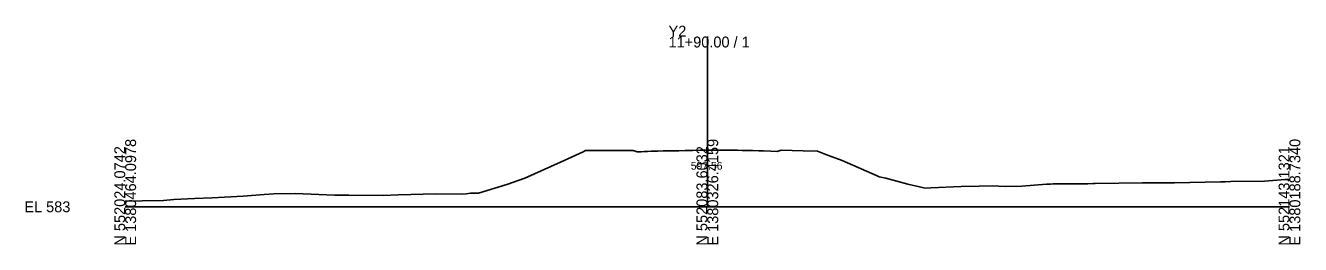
# Model space of a CAD drawing. Extents: x -26 to 303, y -10 to 2047.
# Drawn here: x -25.7 to 302.8, y 1990.3 to 2046.6 of the extents above; entities that cross this region are included whole.
import ezdxf

# ---------------------------------------------------------------- set-up
doc = ezdxf.new("R2010")
doc.units = 0
for name, color, linetype in [('Exist Cross Section Cell', 7, 'Continuous'), ('Exist XS Center Line Elevation Label', 7, 'Continuous'), ('Exist XS Ground Line', 7, 'Continuous')]:
    doc.layers.add(name, color=color, linetype=linetype)

msp = doc.modelspace()

# ---------------------------------------------------------------- linework, layer by layer
at = {"layer": 'Exist Cross Section Cell'}
for p, q in [((150, 2000), (150, 2043.8)), ((0, 2000), (150, 2000)), ((150, 2000), (300, 2000))]:
    msp.add_line(p, q, dxfattribs=at)
at = {"layer": 'Exist XS Ground Line'}
for p, q in [((112.15, 2011.49), (118.01, 2014.14)), ((118.01, 2014.14), (118.57, 2014.45)), ((118.57, 2014.45), (122.81, 2014.46)), ((122.81, 2014.46), (130.89, 2014.49)), ((130.89, 2014.49), (131.93, 2014.11)), ((131.93, 2014.11), (132.98, 2014.17)), ((132.98, 2014.17), (133.71, 2014.22)), ((133.71, 2014.22), (134.57, 2014.27)), ((134.57, 2014.27), (135.51, 2014.3)), ((135.51, 2014.3), (137.21, 2014.35)), ((137.21, 2014.35), (138.59, 2014.37)), ((138.59, 2014.37), (139.93, 2014.39)), ((139.93, 2014.39), (141.76, 2014.42)), ((141.76, 2014.42), (142.67, 2014.43)), ((142.67, 2014.43), (144.3, 2014.45)), ((144.3, 2014.45), (145.39, 2014.47)), ((145.39, 2014.47), (146.19, 2014.5)), ((146.19, 2014.5), (148.17, 2014.54)), ((148.17, 2014.54), (150, 2014.56)), ((150, 2014.56), (150.82, 2014.57)), ((150.82, 2014.57), (152.92, 2014.56)), ((152.92, 2014.56), (153.53, 2014.56)), ((153.53, 2014.56), (154.34, 2014.56)), ((154.34, 2014.56), (156.25, 2014.54)), ((156.25, 2014.54), (157.73, 2014.53)), ((157.73, 2014.53), (158.98, 2014.52)), ((158.98, 2014.52), (159.48, 2014.51)), ((159.48, 2014.51), (160.63, 2014.48)), ((160.63, 2014.48), (161.39, 2014.46)), ((161.39, 2014.46), (161.72, 2014.45)), ((161.72, 2014.45), (163.3, 2014.4)), ((163.3, 2014.4), (164.43, 2014.38)), ((164.43, 2014.38), (166.35, 2014.32)), ((166.35, 2014.32), (167.99, 2014.21)), ((167.99, 2014.21), (169, 2014.6)), ((169, 2014.6), (174.71, 2014.4)), ((174.71, 2014.4), (178.42, 2014.28)), ((178.42, 2014.28), (180.54, 2013.46)), ((103.01, 2007.39), (112.15, 2011.49)), ((180.54, 2013.46), (184.72, 2011.93)), ((184.72, 2011.93), (193.75, 2007.94)), ((98.35, 2005.74), (103.01, 2007.39)), ((193.75, 2007.94), (194.26, 2007.72)), ((194.26, 2007.72), (195.99, 2007.34)), ((195.99, 2007.34), (201.64, 2005.86)), ((91.05, 2003.48), (98.35, 2005.74)), ((201.64, 2005.86), (205.76, 2004.9)), ((205.76, 2004.9), (206.31, 2004.78)), ((206.31, 2004.78), (207.62, 2004.84)), ((207.62, 2004.84), (215.43, 2005.26)), ((215.43, 2005.26), (220.06, 2005.3)), ((220.06, 2005.3), (223.48, 2005.36)), ((223.48, 2005.36), (226.74, 2005.24)), ((226.74, 2005.24), (231.01, 2005.29)), ((231.01, 2005.29), (237.43, 2005.79)), ((237.43, 2005.79), (238.04, 2005.83)), ((238.04, 2005.83), (238.46, 2005.86)), ((238.46, 2005.86), (239.13, 2005.91)), ((239.13, 2005.91), (242.6, 2005.92)), ((242.6, 2005.92), (248.04, 2005.94)), ((248.04, 2005.94), (249.31, 2005.96)), ((249.31, 2005.96), (249.89, 2005.96)), ((249.89, 2005.96), (262.12, 2006.13)), ((262.12, 2006.13), (265.78, 2006.18)), ((265.78, 2006.18), (270.36, 2006.14)), ((270.36, 2006.14), (282.22, 2006.42)), ((282.22, 2006.42), (282.83, 2006.46)), ((282.83, 2006.46), (283.44, 2006.46)), ((283.44, 2006.46), (284.91, 2006.48)), ((284.91, 2006.48), (293.55, 2006.63)), ((293.55, 2006.63), (298.9, 2006.99)), ((298.9, 2006.99), (300, 2007.06)), ((0, 2001.43), (4.38, 2001.54)), ((4.38, 2001.54), (9.87, 2001.65)), ((9.87, 2001.65), (12.52, 2001.89)), ((12.52, 2001.89), (17.88, 2002.11)), ((17.88, 2002.11), (22.43, 2002.27)), ((22.43, 2002.27), (25.6, 2002.47)), ((25.6, 2002.47), (30.39, 2002.74)), ((30.39, 2002.74), (35.83, 2003.18)), ((35.83, 2003.18), (38.32, 2003.3)), ((38.32, 2003.3), (43.75, 2003.4)), ((43.75, 2003.4), (53.98, 2003.02)), ((53.98, 2003.02), (54.69, 2002.99)), ((54.69, 2002.99), (55.39, 2003)), ((55.39, 2003), (57.61, 2002.97)), ((57.61, 2002.97), (66.49, 2002.93)), ((66.49, 2002.93), (70.32, 2003.06)), ((70.32, 2003.06), (80.01, 2003.31)), ((80.01, 2003.31), (86.67, 2003.23)), ((86.67, 2003.23), (87.88, 2003.32)), ((87.88, 2003.32), (89, 2003.47)), ((89, 2003.47), (91.05, 2003.48))]:
    msp.add_line(p, q, dxfattribs=at)

# ---------------------------------------------------------------- texts
at = {"layer": 'Exist Cross Section Cell'}
for s, p in [('Y2', (140, 2043.8)), ('11+90.00 / 1', (140, 2041)), ('EL 583', (-26, 1998.6))]:
    msp.add_text(s, height=2.8, dxfattribs=at).set_placement(p)
for s, p in [('E 1380464.0978', (2.8, 1990)), ('E 1380326.4159', (152.8, 1990)), ('E 1380188.7340', (302.8, 1990)), ('N 552024.0742', (0, 1990)), ('N 552083.6032', (150, 1990)), ('N 552143.1321', (300, 1990))]:
    msp.add_text(s, height=2.8, rotation=90, dxfattribs=at).set_placement(p)
at = {"layer": 'Exist XS Center Line Elevation Label'}
msp.add_text('597.56', height=2, dxfattribs=at).set_placement((145.73, 2009.56))

doc.saveas('drawing.dxf')
